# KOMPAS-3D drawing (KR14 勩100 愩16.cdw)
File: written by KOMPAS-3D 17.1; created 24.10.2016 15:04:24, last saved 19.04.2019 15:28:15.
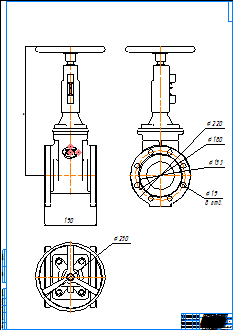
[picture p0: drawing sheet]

Sheet 1: A0, portrait

Title block, sheet 1: name: KR14 Ду100 Ру16; material: Внимание! Данный продукт является объектом авторского права ООО «Торговый Дом АДЛ». / Запрещается изменение, копирование, распространение / (в том числе путем копирования на другие сайты и ресурсы в Интернете) / или любое иное использование информации и объектов без предварительного / согласия правообладателя (ООО «Торговый Дом АДЛ»).; mass: 41,1; sheets: 1; organisation: ООО "Торговый дом АДЛ"; sheet format: A0; stored path: \\adlc.lan\data\АДЛ_ПКД\3D-модели\ADL production\Клиновые задвижки серии KR ГРАНАР\Клиновые задвижки KR14\kompas 2d\KR14 Ду100 Ру16.cdw

Views: Вид 1
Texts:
  Klimkovich
  ADL
Dimensions and other numbers on the sheet: 190; 464; 1:1; 1; 41,1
